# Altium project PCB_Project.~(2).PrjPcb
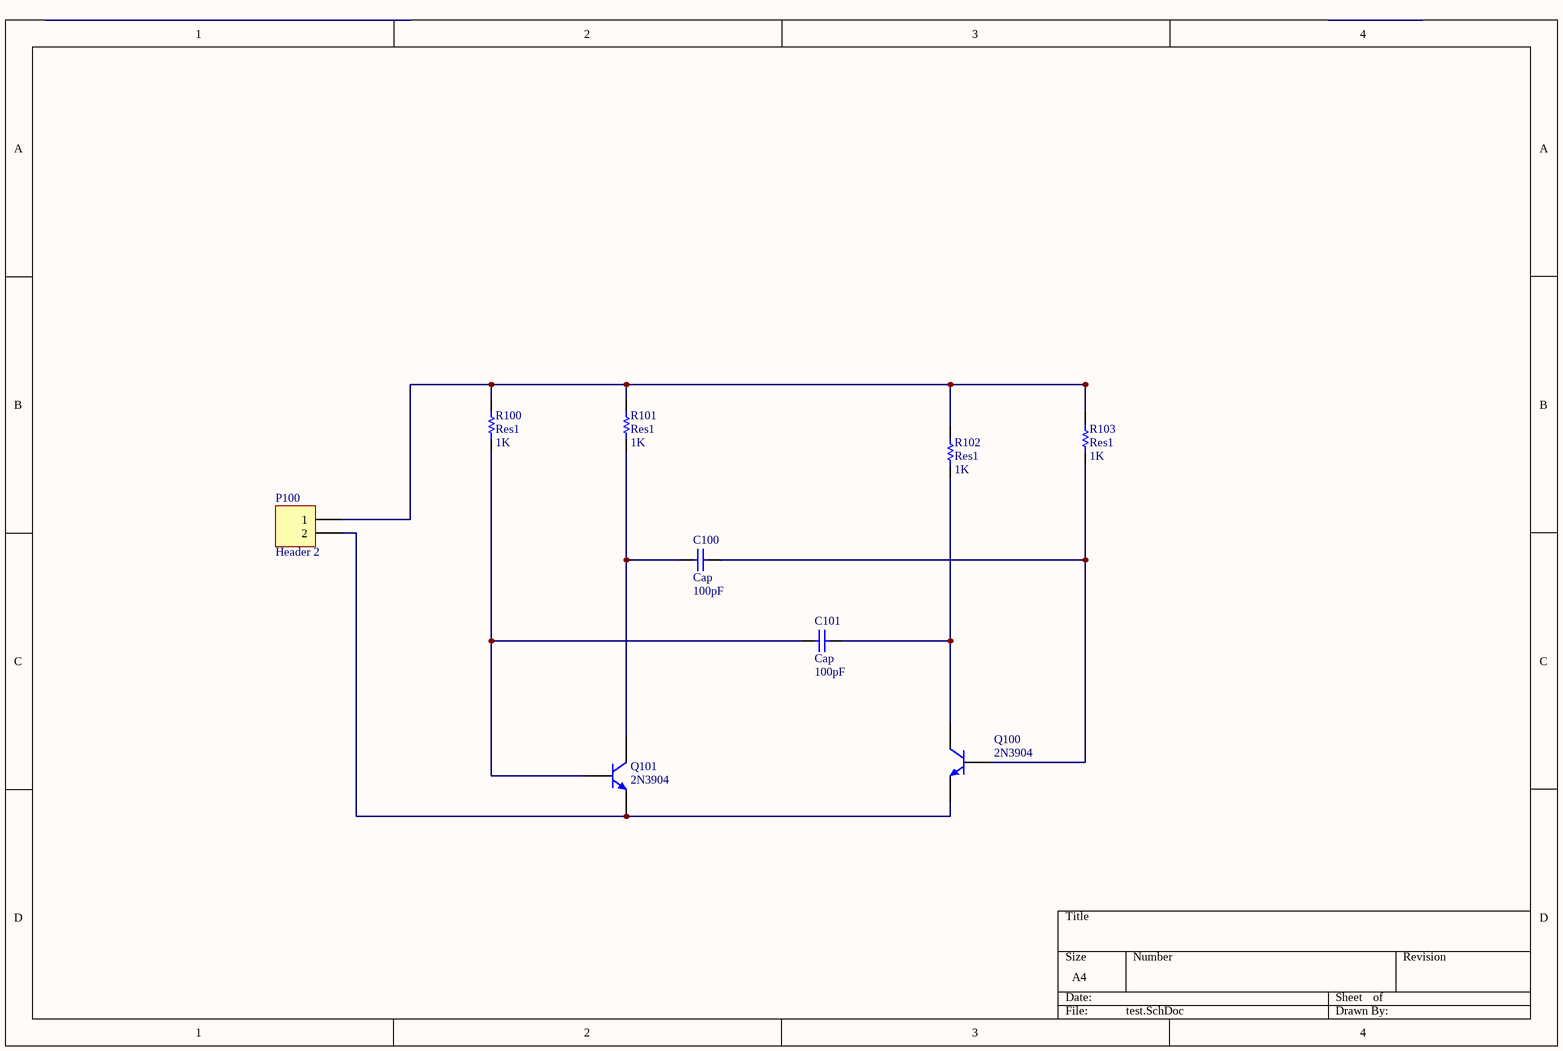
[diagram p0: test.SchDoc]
1 sheet, 9 parts. Net scope: global (net labels, ports and power ports of the same name join across sheets).
Board file: MV-PRO.PcbDoc

## Sheet test.SchDoc
size A4

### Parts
C100  Cap  value 100pF  [RAD-0.3]
C101  Cap  value 100pF  [RAD-0.3]
P100  Header 2  [HDR1X2]
Q100  2N3904  [TO-92A]
Q101  2N3904  [TO-92A]
R100  Res1  value 1K  [AXIAL-0.3]
R101  Res1  value 1K  [AXIAL-0.3]
R102  Res1  value 1K  [AXIAL-0.3]
R103  Res1  value 1K  [AXIAL-0.3]

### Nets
NetC100_1: C100.1 Q101.3(C) R101.2
NetC100_2: C100.2 Q100.2(B) R103.2
NetC101_1: C101.1 Q101.2(B) R100.2
NetC101_2: C101.2 Q100.3(C) R102.2
NetP100_1: P100.1 R100.1 R101.1 R102.1 R103.1
NetP100_2: P100.2 Q100.1(E) Q101.1(E)

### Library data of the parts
C100 C101 = Cap: Capacitor
P100 = Header 2: Header, 2-Pin
Q100 Q101 = 2N3904: NPN General Purpose Amplifier
R100-R103 = Res1: Resistor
